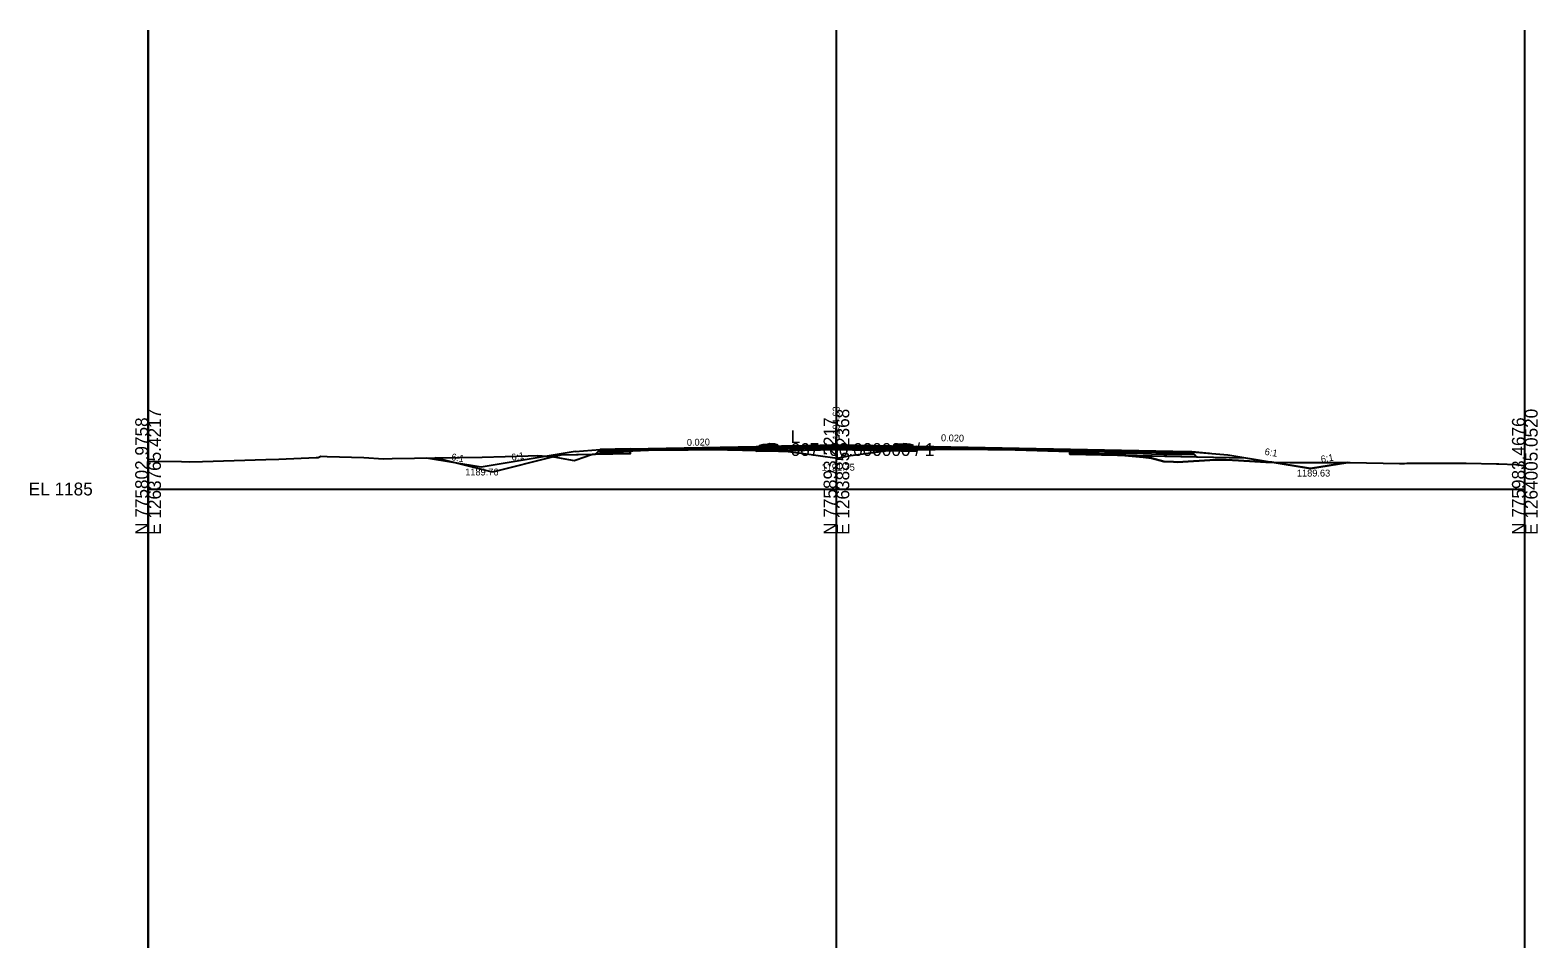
# Model space of a CAD drawing. Extents: x -41 to 1262860, y -100 to 777489.
# Drawn here: x -25.7 to 302.8, y 2015 to 2215 of the extents above; entities that cross this region are included whole.
import ezdxf

# ---------------------------------------------------------------- set-up
doc = ezdxf.new("R2010")
doc.units = 0
for name, color, linetype in [('Exist Cross Section Cell', 7, 'Continuous'), ('Exist XS Center Line Elevation Label', 7, 'Continuous'), ('Exist XS Ground Line', 7, 'Continuous'), ('Prop CMT Pvmt Course 1', 7, 'Continuous'), ('Prop CMT Pvmt Course 4', 7, 'Continuous'), ('Prop CMT Pvmt Surface', 7, 'Continuous'), ('Prop CMT Shld Paved Course 1', 7, 'Continuous'), ('Prop CMT Shld Paved Course 2', 7, 'Continuous'), ('Prop CMT Shld Paved Course 4', 7, 'Continuous'), ('Prop CMT Subgrade Earthwork', 7, 'Continuous'), ('Prop Conc Curb and Gutter', 7, 'Continuous'), ('Prop Conc Island Cover', 7, 'Continuous'), ('Prop XS Ditch Standard Text', 7, 'Continuous'), ('Prop XS Earthwork Shape', 7, 'Continuous'), ('Prop XS Exc Vertical Line 1', 7, 'Continuous'), ('Prop XS Exc Vertical Line 2', 7, 'Continuous'), ('Prop XS Exc Vertical Line 3', 7, 'Continuous'), ('Prop XS Finish Grade', 7, 'Continuous'), ('Prop XS Hydro Elevations', 7, 'Continuous'), ('Prop XS SE Text', 7, 'Continuous'), ('Prop XS Side Slope Text', 7, 'Continuous'), ('Scratch_Level_4', 7, 'Continuous'), ('Scratch_Level_6', 7, 'Continuous')]:
    doc.layers.add(name, color=color, linetype=linetype)

msp = doc.modelspace()

# ---------------------------------------------------------------- linework, layer by layer
at = {"layer": 'Exist Cross Section Cell'}
for p, q in [((150, 2115), (150, 2125)), ((0, 2115), (150, 2115)), ((150, 2115), (300, 2115))]:
    msp.add_line(p, q, dxfattribs=at)
at = {"layer": 'Exist XS Ground Line'}
msp.add_lwpolyline([(0, 2121.1), (7.28, 2120.96), (9, 2120.91), (11.84, 2121), (25.66, 2121.4), (28.5, 2121.5), (36.6, 2121.86), (37.05, 2121.89), (37.52, 2122.1), (37.54, 2122.12), (39.01, 2122.1), (46.99, 2121.85), (51.33, 2121.55), (53.21, 2121.63), (67.89, 2121.87), (72.81, 2121.96), (82.79, 2122.24), (84.95, 2122.28), (85.86, 2122.26), (88.44, 2121.98), (91.64, 2121.4), (92.82, 2121.21), (93.31, 2121.38), (96.62, 2122.5), (98.48, 2122.76), (100.46, 2123.02), (101.19, 2123.03), (103.06, 2123.23), (104.43, 2123.28), (105.65, 2123.33), (109.08, 2123.45), (110.77, 2123.51), (117.66, 2123.56), (122.97, 2123.62), (129.5, 2123.49), (135.51, 2123.35), (137.36, 2123.28), (138.91, 2123.22), (144.02, 2122.59), (146, 2122.31), (150.14, 2121.74), (153.1, 2122.3), (160.23, 2123.25), (161.1, 2123.36), (164.43, 2123.53), (164.58, 2123.53), (176.58, 2123.68), (176.76, 2123.68), (176.95, 2123.68), (188.98, 2123.55), (200.89, 2123.17), (201.14, 2123.16), (204.6, 2123.02), (204.66, 2123.01), (204.95, 2122.99), (207.23, 2122.78), (216.82, 2121.96), (218.64, 2121.72), (221.36, 2120.99), (223.45, 2120.92), (224.32, 2120.88), (232.51, 2121.34), (234.9, 2121.37), (237.58, 2121.2), (243.58, 2120.88), (248.83, 2120.79), (253.78, 2120.74), (261.94, 2120.81), (272.68, 2120.59), (273.77, 2120.58), (274.31, 2120.6), (278.13, 2120.61), (287.2, 2120.66), (293.84, 2120.51), (294.36, 2120.52), (298.01, 2120.34), (299.18, 2120.16), (300, 2120.12)], dxfattribs=at)
at = {"layer": 'Prop CMT Pvmt Course 1'}
for p, q in [((132.5, 2124.28), (138, 2124.39)), ((132.5, 2124.03), (150, 2124.38)), ((150, 2124.38), (167.5, 2124.03)), ((162, 2124.39), (167.5, 2124.28))]:
    msp.add_line(p, q, dxfattribs=at)
for points in [[(105.05, 2123.48), (105.05, 2123.73), (124.85, 2124.13), (124.85, 2124.13), (124.85, 2124.13), (126.11, 2124.15), (126.11, 2124.15), (132.5, 2124.28), (132.5, 2124.03), (132.5, 2124.03), (126.11, 2123.9), (126.11, 2123.9), (124.85, 2123.88), (124.85, 2123.88), (124.85, 2123.88), (105.05, 2123.48), (105.04, 2123.48)], [(223.29, 2122.92), (223.29, 2123.17), (167.5, 2124.28), (167.5, 2124.28), (167.5, 2124.03), (167.5, 2124.03), (167.5, 2124.03), (223.29, 2122.92), (223.29, 2122.92)]]:
    msp.add_lwpolyline(points, dxfattribs=at)
at = {"layer": 'Prop CMT Pvmt Course 4'}
for p, q in [((97.9, 2123.01), (97.44, 2122.54)), ((105.05, 2122.69), (97.44, 2122.54)), ((132.5, 2123.7), (132.5, 2123.24)), ((132.5, 2123.24), (150, 2123.59)), ((150, 2123.59), (167.5, 2123.24)), ((167.5, 2123.7), (167.5, 2123.24))]:
    msp.add_line(p, q, dxfattribs=at)
at = {"layer": 'Prop CMT Pvmt Surface'}
for p, q in [((98.5, 2123.6), (105.05, 2123.73)), ((105.05, 2123.73), (132.5, 2124.28)), ((132.5, 2124.28), (150, 2124.63)), ((150, 2124.63), (167.5, 2124.28)), ((167.5, 2124.28), (223.29, 2123.17)), ((223.29, 2123.17), (227.41, 2123.08))]:
    msp.add_line(p, q, dxfattribs=at)
at = {"layer": 'Prop CMT Shld Paved Course 1'}
for p, q in [((98.24, 2123.35), (98.5, 2123.6)), ((103.62, 2123.45), (98.24, 2123.35)), ((105.05, 2123.73), (98.5, 2123.6)), ((100.83, 2123.4), (100.78, 2123.4)), ((100.83, 2123.4), (100.83, 2123.4)), ((103.62, 2123.7), (103.62, 2123.7)), ((105.04, 2123.48), (103.62, 2123.45)), ((103.62, 2123.45), (103.62, 2123.45)), ((105.05, 2123.73), (105.05, 2123.48)), ((105.05, 2123.48), (105.05, 2123.48))]:
    msp.add_line(p, q, dxfattribs=at)
for points in [[(138, 2124.39), (139.31, 2124.42), (150, 2124.63), (150, 2124.63), (162, 2124.39), (162, 2124.39)], [(223.29, 2123.17), (223.29, 2123.17), (223.29, 2122.92), (223.29, 2122.92), (223.29, 2122.92), (227.66, 2122.83), (227.41, 2123.08), (227.41, 2123.08), (223.29, 2123.17)]]:
    msp.add_lwpolyline(points, dxfattribs=at)
at = {"layer": 'Prop CMT Shld Paved Course 2'}
for p, q in [((97.9, 2123.01), (98.24, 2123.35)), ((100.83, 2123.07), (97.9, 2123.01)), ((100.44, 2123.06), (100.44, 2123.06)), ((100.78, 2123.4), (100.83, 2123.4)), ((100.83, 2123.4), (103.62, 2123.45)), ((100.83, 2123.4), (100.83, 2123.4)), ((103.62, 2123.12), (100.83, 2123.07)), ((100.83, 2123.07), (100.83, 2123.07)), ((103.62, 2123.45), (105.04, 2123.48)), ((103.62, 2123.45), (103.62, 2123.45)), ((105.05, 2123.15), (103.62, 2123.12)), ((103.62, 2123.12), (103.62, 2123.12)), ((105.05, 2123.48), (105.65, 2123.49)), ((105.05, 2123.48), (105.05, 2123.15)), ((105.05, 2123.31), (105.05, 2123.48)), ((105.65, 2123.33), (105.05, 2123.31)), ((105.05, 2123.31), (105.05, 2123.31)), ((105.05, 2123.15), (105.05, 2123.15)), ((105.65, 2123.49), (109.08, 2123.56)), ((105.65, 2123.49), (105.65, 2123.49)), ((105.65, 2123.49), (105.65, 2123.49)), ((105.65, 2123.49), (105.65, 2123.49)), ((109.08, 2123.45), (105.65, 2123.33)), ((105.65, 2123.33), (105.65, 2123.33)), ((105.65, 2123.33), (105.65, 2123.33)), ((105.65, 2123.33), (105.65, 2123.33)), ((109.08, 2123.56), (110.77, 2123.6)), ((109.08, 2123.56), (109.08, 2123.56)), ((110.77, 2123.51), (109.08, 2123.45)), ((109.08, 2123.45), (109.08, 2123.45)), ((110.77, 2123.6), (117.66, 2123.74)), ((117.66, 2123.56), (110.77, 2123.51)), ((117.66, 2123.74), (122.97, 2123.84)), ((117.66, 2123.74), (117.66, 2123.74)), ((122.97, 2123.62), (117.66, 2123.56)), ((117.66, 2123.56), (117.66, 2123.56)), ((122.97, 2123.84), (124.85, 2123.88)), ((122.97, 2123.84), (122.97, 2123.84)), ((122.97, 2123.84), (122.97, 2123.84)), ((122.97, 2123.84), (122.97, 2123.84)), ((124.85, 2123.58), (122.97, 2123.62)), ((122.97, 2123.62), (122.97, 2123.62)), ((122.97, 2123.62), (122.97, 2123.62)), ((122.97, 2123.62), (122.97, 2123.62)), ((122.97, 2123.62), (122.97, 2123.62)), ((124.85, 2123.88), (126.11, 2123.9)), ((124.85, 2123.88), (124.85, 2123.88)), ((125.77, 2123.56), (124.85, 2123.58)), ((126.11, 2123.57), (125.77, 2123.56)), ((125.77, 2123.56), (125.77, 2123.56)), ((126.11, 2123.9), (129.5, 2123.97)), ((126.11, 2123.9), (126.11, 2123.9)), ((129.5, 2123.64), (126.11, 2123.57)), ((126.11, 2123.57), (126.11, 2123.57)), ((129.5, 2123.97), (132.5, 2124.03)), ((129.5, 2123.97), (129.5, 2123.97)), ((132.5, 2123.7), (129.5, 2123.64)), ((129.5, 2123.64), (129.5, 2123.64)), ((132.5, 2123.7), (150, 2124.05)), ((132.5, 2124.03), (132.5, 2124.03)), ((132.5, 2124.03), (132.5, 2123.7)), ((132.5, 2123.7), (132.5, 2123.7)), ((132.5, 2123.7), (132.5, 2123.7)), ((150, 2124.05), (167.5, 2123.7)), ((176.58, 2123.85), (167.5, 2124.03)), ((167.5, 2124.03), (167.5, 2124.03)), ((167.5, 2124.03), (167.5, 2123.7)), ((167.5, 2123.7), (167.5, 2123.7)), ((167.5, 2123.7), (167.5, 2123.7)), ((167.5, 2123.7), (171.53, 2123.62)), ((171.53, 2123.62), (176.58, 2123.68)), ((171.53, 2123.62), (171.53, 2123.62)), ((176.76, 2123.85), (176.58, 2123.85)), ((176.58, 2123.85), (176.58, 2123.85)), ((176.58, 2123.68), (176.58, 2123.68)), ((176.58, 2123.68), (176.76, 2123.68)), ((176.95, 2123.84), (176.76, 2123.85)), ((176.76, 2123.68), (176.95, 2123.68)), ((188.98, 2123.6), (176.95, 2123.84)), ((176.95, 2123.84), (176.95, 2123.84)), ((176.95, 2123.68), (176.95, 2123.68)), ((176.95, 2123.68), (188.98, 2123.55)), ((200.89, 2123.36), (188.98, 2123.6)), ((188.98, 2123.6), (188.98, 2123.6)), ((188.98, 2123.6), (188.98, 2123.6)), ((188.98, 2123.55), (188.98, 2123.55)), ((188.98, 2123.55), (188.98, 2123.55)), ((188.98, 2123.55), (200.89, 2123.17)), ((201.14, 2123.36), (200.89, 2123.36)), ((200.89, 2123.36), (200.89, 2123.36)), ((200.89, 2123.17), (200.89, 2123.17)), ((200.89, 2123.17), (200.89, 2123.03)), ((200.89, 2123.03), (207.23, 2122.9)), ((204.6, 2123.29), (201.14, 2123.36)), ((201.14, 2123.36), (201.14, 2123.36)), ((204.66, 2123.29), (204.6, 2123.29)), ((204.6, 2123.29), (204.6, 2123.29)), ((204.95, 2123.28), (204.66, 2123.29)), ((207.23, 2123.24), (204.95, 2123.28)), ((216.82, 2123.05), (207.23, 2123.24)), ((207.23, 2123.24), (207.23, 2123.24)), ((207.23, 2123.24), (207.23, 2123.24)), ((207.23, 2123.24), (207.23, 2123.24)), ((207.23, 2123.24), (207.23, 2123.24)), ((207.23, 2123.24), (207.23, 2123.24)), ((207.23, 2122.9), (207.23, 2122.9)), ((207.23, 2122.9), (207.23, 2122.9)), ((207.23, 2122.9), (207.23, 2122.9)), ((207.23, 2122.9), (207.23, 2122.9)), ((207.23, 2122.9), (207.23, 2122.9)), ((207.23, 2122.9), (216.82, 2122.71)), ((218.64, 2123.01), (216.82, 2123.05)), ((216.82, 2123.05), (216.82, 2123.05)), ((216.82, 2123.05), (216.82, 2123.05)), ((216.82, 2122.71), (216.82, 2122.71)), ((216.82, 2122.71), (216.82, 2122.71)), ((216.82, 2122.71), (218.64, 2122.68)), ((221.36, 2122.95), (218.64, 2123.01)), ((218.64, 2122.68), (221.36, 2122.62)), ((223.29, 2122.92), (221.36, 2122.95)), ((221.36, 2122.95), (221.36, 2122.95)), ((221.36, 2122.62), (221.36, 2122.62)), ((221.36, 2122.62), (223.29, 2122.58)), ((223.29, 2122.58), (223.29, 2122.92)), ((223.29, 2122.58), (223.29, 2122.58))]:
    msp.add_line(p, q, dxfattribs=at)
msp.add_lwpolyline([(223.29, 2122.92), (223.29, 2122.92), (223.29, 2122.58), (223.29, 2122.58), (223.29, 2122.58), (228, 2122.49), (227.66, 2122.83), (227.66, 2122.83), (223.29, 2122.92)], dxfattribs=at)
at = {"layer": 'Prop CMT Shld Paved Course 4'}
for p, q in [((100.44, 2123.06), (100.83, 2123.07)), ((100.83, 2123.07), (103.62, 2123.12)), ((100.83, 2123.07), (100.83, 2123.07)), ((103.62, 2123.12), (105.04, 2123.15)), ((103.62, 2123.12), (103.62, 2123.12)), ((105.05, 2123.15), (105.05, 2122.69)), ((129.5, 2123.49), (125.77, 2123.56)), ((129.5, 2123.49), (132.5, 2123.42)), ((167.5, 2123.57), (171.53, 2123.62)), ((200.89, 2123.03), (200.89, 2122.57)), ((200.89, 2122.57), (228.47, 2122.02)), ((223.29, 2122.58), (223.29, 2122.58)), ((228, 2122.49), (223.29, 2122.58)), ((228, 2122.49), (228, 2122.49)), ((228, 2122.49), (228.47, 2122.02))]:
    msp.add_line(p, q, dxfattribs=at)
at = {"layer": 'Prop CMT Subgrade Earthwork'}
for p, q in [((105.05, 2122.69), (89.94, 2122.39)), ((105.05, 2122.69), (105.05, 2123.31)), ((132.5, 2123.24), (150, 2123.59)), ((132.5, 2123.42), (132.5, 2123.24)), ((167.5, 2123.24), (150, 2123.59)), ((167.5, 2123.57), (167.5, 2123.24)), ((200.89, 2123.17), (200.89, 2122.57)), ((200.89, 2122.57), (239.17, 2121.81))]:
    msp.add_line(p, q, dxfattribs=at)
at = {"layer": 'Prop Conc Curb and Gutter'}
for p, q in [((133.25, 2124.3), (133.26, 2124.46)), ((133.25, 2124.3), (133.25, 2124.3)), ((133.25, 2124.3), (133.25, 2124.17)), ((135.01, 2124.3), (133.25, 2124.3)), ((133.25, 2124.3), (133.25, 2124.3)), ((133.25, 2124.17), (133.25, 2124.17)), ((133.25, 2124.17), (135.01, 2124.17)), ((133.26, 2124.46), (134.01, 2124.71)), ((133.26, 2124.46), (133.26, 2124.46)), ((134.01, 2124.71), (135.01, 2124.73)), ((134.01, 2124.71), (134.01, 2124.71)), ((135.01, 2124.73), (135.01, 2124.3)), ((135.01, 2124.17), (135.01, 2124.3)), ((135.01, 2124.3), (135.01, 2124.3)), ((135.01, 2124.17), (135.01, 2124.17)), ((135.01, 2124.17), (135.01, 2124.17)), ((136.49, 2124.79), (135.49, 2124.81)), ((135.49, 2124.81), (135.49, 2124.38)), ((137.25, 2124.38), (135.49, 2124.38)), ((135.49, 2124.38), (135.49, 2124.25)), ((135.49, 2124.38), (135.49, 2124.38)), ((135.49, 2124.25), (135.49, 2124.25)), ((135.49, 2124.25), (137.25, 2124.25)), ((137.24, 2124.54), (136.49, 2124.79)), ((136.49, 2124.79), (136.49, 2124.79)), ((137.25, 2124.38), (137.24, 2124.54)), ((137.24, 2124.54), (137.24, 2124.54)), ((137.25, 2124.25), (137.25, 2124.38)), ((137.25, 2124.38), (137.25, 2124.38)), ((137.25, 2124.38), (137.25, 2124.38)), ((137.25, 2124.25), (137.25, 2124.25)), ((137.25, 2124.25), (137.25, 2124.25)), ((162.75, 2124.38), (162.76, 2124.54)), ((162.75, 2124.38), (162.75, 2124.38)), ((162.75, 2124.38), (162.75, 2124.25)), ((164.51, 2124.38), (162.75, 2124.38)), ((162.75, 2124.38), (162.75, 2124.38)), ((162.75, 2124.25), (162.75, 2124.25)), ((162.75, 2124.25), (164.51, 2124.25)), ((162.76, 2124.54), (163.51, 2124.79)), ((162.76, 2124.54), (162.76, 2124.54)), ((163.51, 2124.79), (164.51, 2124.81)), ((163.51, 2124.79), (163.51, 2124.79)), ((164.51, 2124.81), (164.51, 2124.38)), ((164.51, 2124.25), (164.51, 2124.38)), ((164.51, 2124.38), (164.51, 2124.38)), ((164.51, 2124.25), (164.51, 2124.25)), ((164.51, 2124.25), (164.51, 2124.25)), ((165.99, 2124.71), (164.99, 2124.73)), ((164.99, 2124.73), (164.99, 2124.3)), ((166.75, 2124.3), (164.99, 2124.3)), ((164.99, 2124.3), (164.99, 2124.17)), ((164.99, 2124.3), (164.99, 2124.3)), ((164.99, 2124.17), (164.99, 2124.17)), ((164.99, 2124.17), (166.75, 2124.17)), ((166.74, 2124.46), (165.99, 2124.71)), ((165.99, 2124.71), (165.99, 2124.71)), ((166.75, 2124.3), (166.74, 2124.46)), ((166.74, 2124.46), (166.74, 2124.46)), ((166.75, 2124.17), (166.75, 2124.3)), ((166.75, 2124.3), (166.75, 2124.3)), ((166.75, 2124.3), (166.75, 2124.3)), ((166.75, 2124.17), (166.75, 2124.17)), ((166.75, 2124.17), (166.75, 2124.17))]:
    msp.add_line(p, q, dxfattribs=at)
at = {"layer": 'Prop Conc Island Cover'}
for p, q in [((135.49, 2124.81), (135.01, 2124.73)), ((135.01, 2124.73), (135.01, 2124.48)), ((135.49, 2124.56), (135.01, 2124.48)), ((135.49, 2124.56), (135.49, 2124.81)), ((135.49, 2124.81), (135.49, 2124.81)), ((135.49, 2124.56), (135.49, 2124.56)), ((164.51, 2124.81), (164.51, 2124.56)), ((164.99, 2124.73), (164.51, 2124.81)), ((164.99, 2124.48), (164.51, 2124.56)), ((164.99, 2124.48), (164.99, 2124.73)), ((164.99, 2124.73), (164.99, 2124.73)), ((164.99, 2124.48), (164.99, 2124.48))]:
    msp.add_line(p, q, dxfattribs=at)
at = {"layer": 'Prop XS Earthwork Shape'}
for points in [[(88.44, 2121.98), (91.64, 2121.4), (92.82, 2121.21), (93.31, 2121.38), (96.62, 2122.5), (96.77, 2122.53), (89.94, 2122.39), (88.34, 2121.99)], [(97.44, 2122.54), (96.77, 2122.53), (97.53, 2122.63)], [(104.43, 2123.28), (105.05, 2123.31), (105.05, 2122.69), (97.44, 2122.54), (97.53, 2122.63), (98.48, 2122.76), (100.46, 2123.02), (101.19, 2123.03), (103.06, 2123.23)], [(132.5, 2123.42), (132.5, 2123.24), (136.34, 2123.32), (135.51, 2123.35)], [(136.34, 2123.32), (137.36, 2123.28), (138.91, 2123.22), (144.02, 2122.59), (146, 2122.31), (150.14, 2121.74), (153.1, 2122.3), (160.23, 2123.25), (161.1, 2123.36), (161.15, 2123.37), (150, 2123.59)], [(161.15, 2123.37), (164.43, 2123.53), (164.58, 2123.53), (167.5, 2123.57), (167.5, 2123.24)], [(207.23, 2122.78), (212.34, 2122.34), (200.89, 2122.57), (200.89, 2123.17), (201.14, 2123.16), (204.6, 2123.02), (204.66, 2123.01), (204.95, 2122.99)], [(212.34, 2122.34), (228.47, 2122.02), (239.17, 2121.81), (244.88, 2120.85), (243.58, 2120.88), (237.58, 2121.2), (234.9, 2121.37), (232.51, 2121.34), (224.32, 2120.88), (223.45, 2120.92), (221.36, 2120.99), (218.64, 2121.72), (216.82, 2121.96)], [(75.05, 2118.67), (62.58, 2121.78), (67.89, 2121.87), (72.81, 2121.96), (82.79, 2122.24), (84.95, 2122.28), (85.86, 2122.26), (88.34, 2121.99)], [(248.83, 2120.79), (253.78, 2120.74), (261.4, 2120.81), (259.15, 2120.43), (253.29, 2119.45), (244.88, 2120.85)]]:
    msp.add_lwpolyline(points, close=True, dxfattribs=at)
at = {"layer": 'Prop XS Exc Vertical Line 1'}
msp.add_line((0, 2015), (0, 2215), dxfattribs=at)
at = {"layer": 'Prop XS Exc Vertical Line 2'}
msp.add_line((150, 2015), (150, 2215), dxfattribs=at)
at = {"layer": 'Prop XS Exc Vertical Line 3'}
msp.add_line((300, 2015), (300, 2215), dxfattribs=at)
at = {"layer": 'Prop XS Finish Grade'}
for p, q in [((93.05, 2123.17), (72.61, 2119.76)), ((93.05, 2123.17), (98.49, 2123.6)), ((98.49, 2123.6), (97.44, 2122.54)), ((227.41, 2123.08), (235.29, 2122.45)), ((227.41, 2123.08), (228.47, 2122.02)), ((235.29, 2122.45), (253.29, 2119.45)), ((72.61, 2119.76), (60.66, 2121.75)), ((253.29, 2119.45), (261.4, 2120.81))]:
    msp.add_line(p, q, dxfattribs=at)
for points in [[(231.29, 2122.77), (227.41, 2123.08), (227.41, 2123.08)], [(259.15, 2120.43), (253.29, 2119.45), (253.29, 2119.45)]]:
    msp.add_lwpolyline(points, dxfattribs=at)
at = {"layer": 'Scratch_Level_4'}
msp.add_line((300, 2015), (300, 2215), dxfattribs=at)
at = {"layer": 'Scratch_Level_6'}
msp.add_line((0, 2215), (0, 2015), dxfattribs=at)

# ---------------------------------------------------------------- texts
at = {"layer": 'Exist Cross Section Cell'}
for s, p in [('E 1263765.4217', (2.8, 2105)), ('E 1263885.2368', (152.8, 2105)), ('E 1264005.0520', (302.8, 2105)), ('N 775802.9758', (0, 2105)), ('N 775893.2217', (150, 2105)), ('N 775983.4676', (300, 2105))]:
    msp.add_text(s, height=2.8, rotation=90, dxfattribs=at).set_placement(p)
for s, p in [('L', (140, 2125)), ('667+00.000000 / 1', (140, 2122.2)), ('EL 1185', (-26, 2113.6))]:
    msp.add_text(s, height=2.8, dxfattribs=at).set_placement(p)
at = {"layer": 'Exist XS Center Line Elevation Label'}
msp.add_text('1191.75', height=1.5, dxfattribs=at).set_placement((146.75, 2119))
at = {"layer": 'Prop XS Ditch Standard Text'}
for s, p in [('1189.76', (69.11, 2117.95)), ('1189.63', (250.34, 2117.72))]:
    msp.add_text(s, height=1.5, dxfattribs=at).set_placement(p)
at = {"layer": 'Prop XS Hydro Elevations'}
msp.add_text('1194.63', height=1.5, rotation=90, dxfattribs=at).set_placement((150.68, 2125.74))
at = {"layer": 'Prop XS SE Text'}
for rotation, p in [(1.1458, (117.42, 2124.4)), (358.8542, (172.77, 2125.42))]:
    msp.add_text('0.020', height=1.5, rotation=rotation, dxfattribs=at).set_placement(p)
at = {"layer": 'Prop XS Side Slope Text'}
for rotation, p in [(349.5519, (65.98, 2121.32)), (9.2189, (79.3, 2121.14)), (350.5377, (243.23, 2122.46)), (9.4809, (255.67, 2120.73))]:
    msp.add_text('6:1', height=1.5, rotation=rotation, dxfattribs=at).set_placement(p)

doc.saveas('drawing.dxf')
